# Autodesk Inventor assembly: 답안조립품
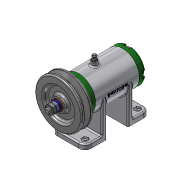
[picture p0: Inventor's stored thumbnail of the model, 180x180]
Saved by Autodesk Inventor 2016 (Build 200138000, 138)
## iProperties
Created: 2017-02
Part Number: 답안조립품
Material: 일반
Document SubType Name: Assembly
Designer: H
Author: H
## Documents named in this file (16)
- C:\Users\CAMTIC\Desktop\470207V1024\답안조립품.iam
- C:\Users\CAMTIC\Desktop\470207V1024\본체.ipt
- C:\Users\CAMTIC\Desktop\470207V1024\V벨트풀리.ipt
- C:\Users\CAMTIC\Desktop\470207V1024\너트 M 8.ipt
- C:\Users\CAMTIC\Desktop\470207V1024\니플 M 6 x 0.75.ipt
- C:\Users\CAMTIC\Desktop\470207V1024\뒤커버.ipt
- C:\Users\CAMTIC\Desktop\470207V1024\베어링 15 x 32 x 9.ipt
- C:\Users\CAMTIC\Desktop\470207V1024\볼트 M 6 x 8.ipt
- C:\Users\CAMTIC\Desktop\470207V1024\볼트 M4 x 12.ipt
- C:\Users\CAMTIC\Desktop\470207V1024\스프링와셔 8.ipt
- C:\Users\CAMTIC\Desktop\470207V1024\앞커버.ipt
- C:\Users\CAMTIC\Desktop\470207V1024\오일 실 15 25 7.ipt
- C:\Users\CAMTIC\Desktop\470207V1024\와셔 6x11.5.ipt
- C:\Users\CAMTIC\Desktop\470207V1024\와셔 8x17.ipt
- C:\Users\CAMTIC\Desktop\470207V1024\축.ipt
- C:\Users\CAMTIC\Desktop\470207V1024\키 3 x 3 x 12.ipt
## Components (11 placed, 3 different names)
1. V벨트풀리:1
2. KS B 2023 6002 - 15 x 32 x 9:1
3. KS B 2023 6002 - 15 x 32 x 9:2
4. ISO 4762 M4 x 12:2
5. ISO 4762 M4 x 12:3
6. ISO 4762 M4 x 12:4
7. ISO 4762 M4 x 12:5
8. ISO 4762 M4 x 12:1
9. ISO 4762 M4 x 12:6
10. ISO 4762 M4 x 12:7
11. ISO 4762 M4 x 12:8
